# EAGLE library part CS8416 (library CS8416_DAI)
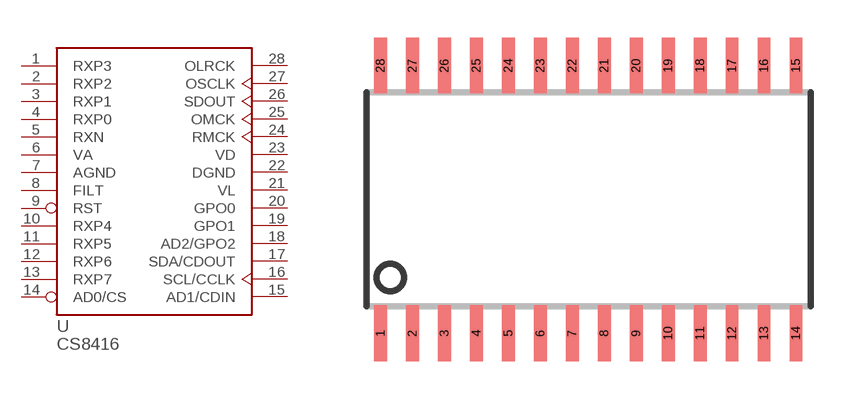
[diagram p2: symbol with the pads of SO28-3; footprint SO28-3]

Designator prefix U

## CS8416  [SO28-3]
1  RXP3  in
2  RXP2  in
3  RXP1  in
4  RXP0  in
5  RXN  in
6  VA  pwr
7  AGND  pwr
8  FILT
9  RST  in
10  RXP4  in
11  RXP5  in
12  RXP6  in
13  RXP7  in
14  AD0/CS  in
15  AD1/CDIN  in
16  SCL/CCLK  in
17  SDA/CDOUT  out
18  AD2/GPO2
19  GPO1
20  GPO0
21  VL  pwr
22  DGND  pwr
23  VD  pwr
24  RMCK  out
25  OMCK  in
26  SDOUT  out
27  OSCLK  out
28  OLRCK  out

## Footprint SO28-3 (pad centres in mm)
Small Outline Package
smd 0.51 x 2.21: 1 -8.255,-5.315; 2 -6.985,-5.315; 3 -5.715,-5.315; 4 -4.445,-5.315; 5 -3.175,-5.315; 6 -1.905,-5.315; 7 -0.635,-5.315; 8 0.635,-5.315; 9 1.905,-5.315; 10 3.175,-5.315; 11 4.445,-5.315; 12 5.715,-5.315; 13 6.985,-5.315; 14 8.255,-5.315; 15 8.255,5.315; 16 6.985,5.315; 17 5.715,5.315; 18 4.445,5.315; 19 3.175,5.315; 20 1.905,5.315; 21 0.635,5.315; 22 -0.635,5.315; 23 -1.905,5.315; 24 -3.175,5.315; 25 -4.445,5.315; 26 -5.715,5.315; 27 -6.985,5.315; 28 -8.255,5.315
